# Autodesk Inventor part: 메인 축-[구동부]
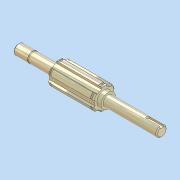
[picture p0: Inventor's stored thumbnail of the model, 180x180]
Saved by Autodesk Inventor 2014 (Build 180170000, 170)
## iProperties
Created: 2012-05
Part Number: 메인 축-[구동부]
Document SubType Name: 모델링
Designer: SeoGD™
Mass: 21.4462 g
Surface Area: 72.5109 cm^2
Volume: 21.4462 cm^3
Density: 1 g/cm^3
Material: 강철, 연강
Appearance: 강철
변환 표준: STEP AP214IS
파일 이름: C:\Users\SeoGD\Desktop\?쒗뿕\硫붿씤 異?.stp
전처리기: Build: 253, Release: 2010 SP1 - Date: Wed 07/29/2009
전송 단위: 밀리미터
불확실성: 0.01
Author: SeoGD™
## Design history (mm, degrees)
sketch "스케치1"
  geometry: L1 (-69.5, 0)-(69.5, 0); L2 (69.5, 0)-(69.5, 5); L3 (69.5, 5)-(55.5, 5); L4 (55.5, 5)-(55.5, 4.8); L5 (55.5, 4.8)-(54.35, 4.8); L6 (54.35, 4.8)-(54.35, 5); L7 (54.35, 5)-(30.5, 5); L8 (30.5, 5)-(30.5, 9); L9 (30.5, 9)-(-13.5, 9); L10 (-13.5, 9)-(-13.5, 7); L11 (-13.5, 7)-(-17.5, 7); L12 (-17.5, 7)-(-17.5, 5); L13 (-17.5, 5)-(-69.5, 5); L14 (-69.5, 5)-(-69.5, 0); 2 further points
  constraints: 28 end point, 9 parallel, 4 collinear, 2 perpendicular, 1 coincident, 1 horizontal, 1 midpoint
  dimensions: "d2" = 1.15 distance between parallel lines of L6 L4; "d3" = 10 diameter of L3 L1; "d4" = 9.6 diameter of L5 L1; "d6" = 44 distance between parallel lines of L10 L8; "d7" = 4 distance between parallel lines of L12 L10; "d8" = 14 diameter of L11 L1; "d9" = 18 diameter of L9 L1; "d33" = 52 distance from line of L12.end L14; "d37" = 39 distance between parallel lines of L8 L2; "d38" = 14 distance between parallel lines of L2 L4
revolve "회전1" sketch "스케치1" stored, may be unused: angle "d10" = 90 deg
sketch "스케치2"
  geometry: L1 (2.5, 10.712)-(2.5, 8.646); L2 (-2.5, 10.712)-(-2.5, 8.646); A1 r 9 centre (0, 0) between (2.5, 8.646) and (-2.5, 8.646) reference; A2 r 11 centre (0, 0) between (2.5, 10.712) and (-2.5, 10.712); 1 further point
  constraints: 4 end point, 4 point on circle, 2 parallel, 1 centre point, 1 coincident, 1 vertical
  dimensions: "d11" = 22 diameter of A2; "d12" = 5 distance between parallel lines of L1 L2
extrude "돌출1" join sketch "스케치2" stored distance "d13" = 10; taper "d14" = 0 deg
chamfer "모따기1" distance "d15" = 1; stored, may be unused: second distance "d16" = 2, angle "d17" = 45 deg
node "작업 평면1"
node "작업 평면2"
sketch "스케치3"
  geometry: L1 (2.5, 10.712)-(2.5, 10.198); L2 (-2.5, 10.712)-(-2.5, 10.198); A1 r 11 centre (0, 0) between (2.5, 10.712) and (-2.5, 10.712) reference; A2 r 10.5 centre (0, 0) between (2.5, 10.198) and (-2.5, 10.198); 1 further point
  constraints: 4 end point, 2 point on circle, 1 centre point, 1 coincident, 1 parallel, 1 vertical
  dimensions: "d19" = 21 diameter of A2
extrude "돌출2" cut sketch "스케치3" distance "d20" = 1.35; taper "d21" = 0 deg
node "작업 평면3"
sketch "스케치4"
  geometry: L1 (-26, -5)-(-26, 5) reference; L2 (-26, 1.5)-(-12.5, 1.5); L3 (-12.5, -1.5)-(-26, -1.5); A1 r 1.5 centre (-12.5, 0) between (-12.5, -1.5) and (-12.5, 1.5); 2 further points
  constraints: 4 end point, 2 perpendicular, 2 point on circle, 2 point on line, 2 tangent, 1 centre point, 1 horizontal alignment, 1 midpoint
  dimensions: "d25" = 3 distance between parallel lines of L3 L2; "d26" = 15 dimension on A1 L1
extrude "돌출3" cut sketch "스케치4" distance "d27" = 1.8; taper "d28" = 0 deg
chamfer "모따기2" distance "d29" = 1; stored, may be unused: second distance "d30" = 2, angle "d31" = 45 deg
node "솔리드1"
node "솔리드 본체"
node "곡면 본체"
mirror "대칭1"
pattern_circular "원형 패턴1" dims "d23" = 360 deg
node "솔리드2"
other parameters: "d18" = -1.65
